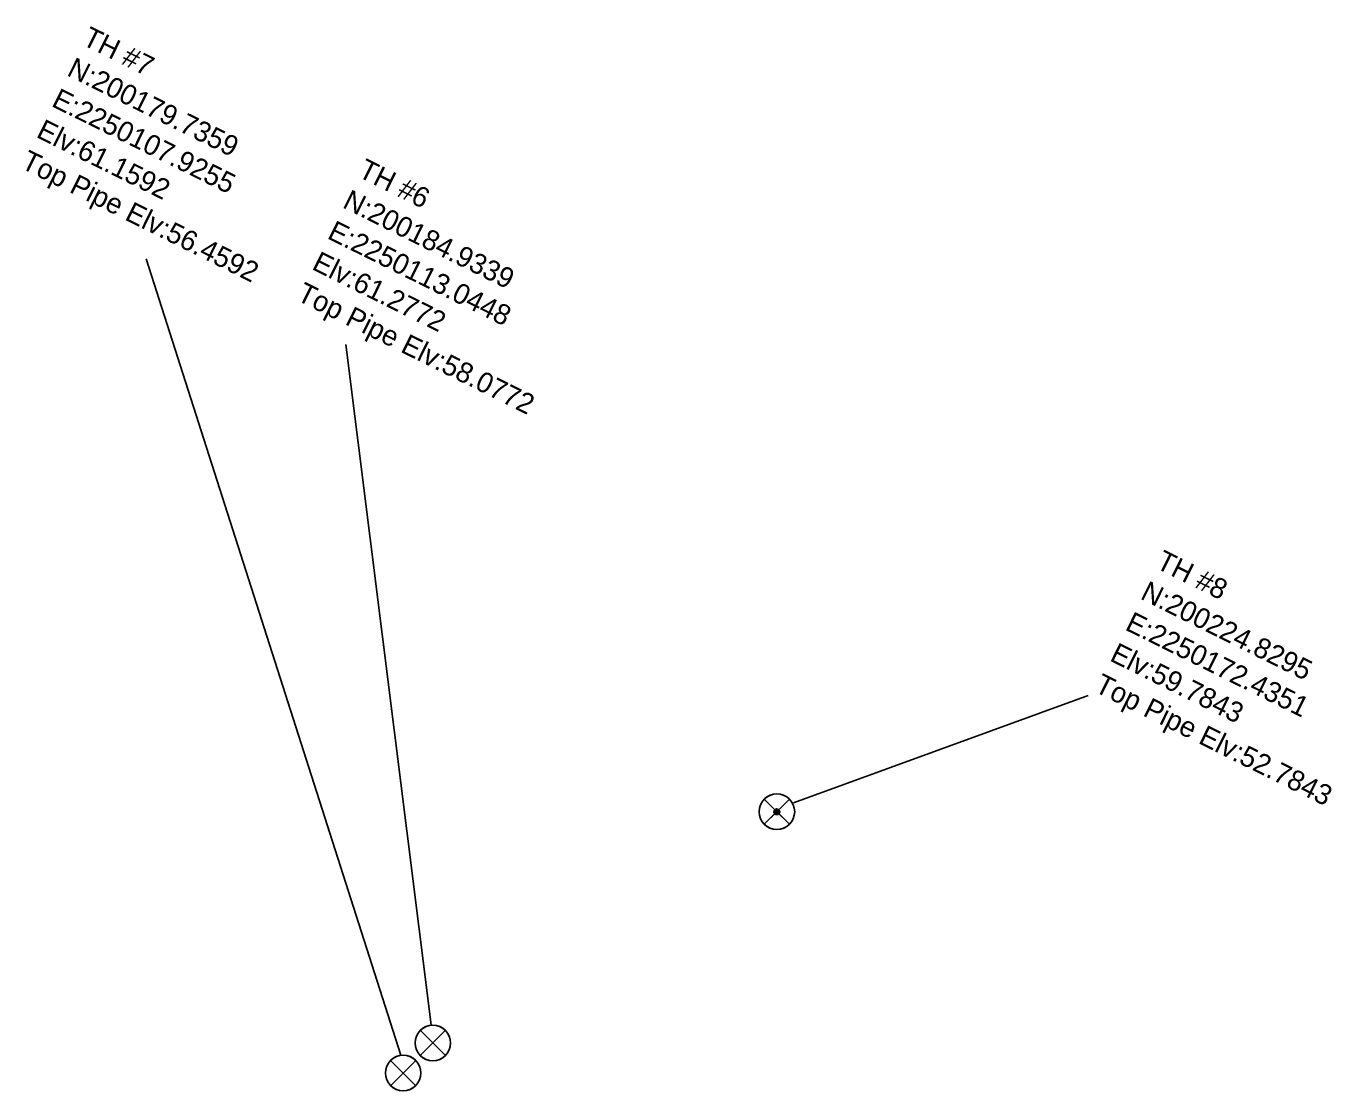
# Model space of a CAD drawing. Extents: x -3 to 2250268, y -3 to 202544.
# Drawn here: x 2250042.8 to 2250268.2, y 200176.7 to 200360.4 of the extents above; entities that cross this region are included whole.
import ezdxf

# ---------------------------------------------------------------- set-up
doc = ezdxf.new("R2010")
doc.units = 0
for name, color, linetype in [('Default', 7, 'Continuous'), ('Exist Utilities Gas Test Hole SUE LOS A CELL', 7, 'Continuous'), ('Exist Utilities Gas Test Hole SUE LOS A Leader', 7, 'Continuous'), ('Exist Utilities Gas Test Hole SUE LOS A Text', 7, 'Continuous'), ('Exist Utilities Sanitary Sewer Test Hole SUE LOS A CELL', 7, 'Continuous'), ('Exist Utilities Sanitary Sewer Test Hole SUE LOS A Leader', 7, 'Continuous'), ('Exist Utilities Sanitary Sewer Test Hole SUE LOS A Text', 7, 'Continuous'), ('Exist Utilities Telephone Test Hole SUE LOS A CELL', 7, 'Continuous'), ('Exist Utilities Telephone Test Hole SUE LOS A Leader', 7, 'Continuous'), ('Exist Utilities Telephone Test Hole SUE LOS A Text', 7, 'Continuous')]:
    doc.layers.add(name, color=color, linetype=linetype)

# ---------------------------------------------------------------- blocks, each defined once
blk = doc.blocks.new('SurveyPointCell')
at = {"layer": 'Default'}
for p, q in [((-0.5, 0), (0.5, 0)), ((0, -0.5), (0, 0.5))]:
    blk.add_line(p, q, dxfattribs=at)
blk.add_circle((0, 0), 0.5, dxfattribs=at)

msp = doc.modelspace()

# ---------------------------------------------------------------- linework, layer by layer
at = {"layer": 'Exist Utilities Gas Test Hole SUE LOS A CELL'}
for points in [[(2250174.61, 200227), (2250170.26, 200222.66), (2250172.44, 200224.83), (2250170.26, 200227), (2250174.61, 200222.66)], [(2250170.26, 200227), (2250172.44, 200224.83), (2250174.61, 200227)], [(2250174.61, 200222.66), (2250172.44, 200224.83), (2250170.26, 200222.66)]]:
    msp.add_lwpolyline(points, dxfattribs=at)
msp.add_circle((2250172.44, 200224.83), 3.07, dxfattribs=at)
for start, end in [(45, 135), (225, 315)]:
    msp.add_arc((2250172.44, 200224.83), 3.07, start, end, dxfattribs=at)
at = {"layer": 'Exist Utilities Gas Test Hole SUE LOS A Leader'}
msp.add_line((2250175.28, 200226.36), (2250226.15, 200244.89), dxfattribs=at)
at = {"layer": 'Exist Utilities Sanitary Sewer Test Hole SUE LOS A CELL'}
for points in [[(2250110.1, 200181.91), (2250105.75, 200177.56), (2250107.93, 200179.74), (2250105.75, 200181.91), (2250110.1, 200177.56)], [(2250105.75, 200181.91), (2250107.93, 200179.74), (2250110.1, 200181.91)], [(2250110.1, 200177.56), (2250107.93, 200179.74), (2250105.75, 200177.56)]]:
    msp.add_lwpolyline(points, dxfattribs=at)
msp.add_circle((2250107.93, 200179.74), 3.07, dxfattribs=at)
for start, end in [(45, 135), (225, 315)]:
    msp.add_arc((2250107.93, 200179.74), 3.07, start, end, dxfattribs=at)
at = {"layer": 'Exist Utilities Sanitary Sewer Test Hole SUE LOS A Leader'}
msp.add_line((2250107.55, 200182.84), (2250063.57, 200320.26), dxfattribs=at)
at = {"layer": 'Exist Utilities Telephone Test Hole SUE LOS A CELL'}
for points in [[(2250115.22, 200187.11), (2250110.87, 200182.76), (2250113.04, 200184.93), (2250110.87, 200187.11), (2250115.22, 200182.76)], [(2250110.87, 200187.11), (2250113.04, 200184.93), (2250115.22, 200187.11)], [(2250115.22, 200182.76), (2250113.04, 200184.93), (2250110.87, 200182.76)]]:
    msp.add_lwpolyline(points, dxfattribs=at)
msp.add_circle((2250113.04, 200184.93), 3.07, dxfattribs=at)
for start, end in [(45, 135), (225, 315)]:
    msp.add_arc((2250113.04, 200184.93), 3.07, start, end, dxfattribs=at)
at = {"layer": 'Exist Utilities Telephone Test Hole SUE LOS A Leader'}
msp.add_line((2250112.75, 200188.06), (2250098.04, 200305.47), dxfattribs=at)

# ---------------------------------------------------------------- block references
at = {"layer": 'Default'}
msp.add_blockref('SurveyPointCell', (2250172.44, 200224.83), dxfattribs=at)

# ---------------------------------------------------------------- texts
at = {"layer": 'Exist Utilities Gas Test Hole SUE LOS A Text'}
for s, p in [('TH #8', (2250237.66, 200266.97)), ('N:200224.8295', (2250235.01, 200261.65)), ('E:2250172.4351', (2250232.36, 200256.32)), ('Elv:59.7843', (2250229.72, 200250.99)), ('Top Pipe Elv:52.7843', (2250227.07, 200245.66))]:
    msp.add_text(s, height=3.5, rotation=333.5785, dxfattribs=at).set_placement(p)
at = {"layer": 'Exist Utilities Sanitary Sewer Test Hole SUE LOS A Text'}
for s, p in [('TH #7', (2250052.34, 200357.31)), ('N:200179.7359', (2250049.7, 200351.99)), ('E:2250107.9255', (2250047.05, 200346.66)), ('Elv:61.1592', (2250044.4, 200341.33)), ('Top Pipe Elv:56.4592', (2250041.75, 200336))]:
    msp.add_text(s, height=3.5, rotation=333.5785, dxfattribs=at).set_placement(p)
at = {"layer": 'Exist Utilities Telephone Test Hole SUE LOS A Text'}
for s, p in [('TH #6', (2250099.94, 200334.51)), ('N:200184.9339', (2250097.29, 200329.18)), ('E:2250113.0448', (2250094.64, 200323.85)), ('Elv:61.2772', (2250091.99, 200318.52)), ('Top Pipe Elv:58.0772', (2250089.35, 200313.19))]:
    msp.add_text(s, height=3.5, rotation=333.5785, dxfattribs=at).set_placement(p)

doc.saveas('drawing.dxf')
